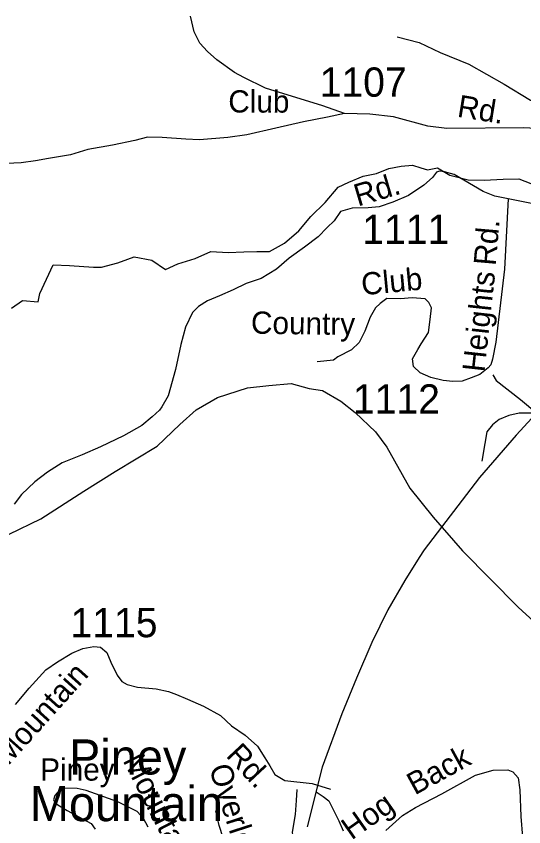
# Model space of a CAD drawing. Extents: x 990631 to 1056237, y 535999 to 585651.
# Drawn here: x 1027764 to 1029934, y 547537 to 550999 of the extents above; entities that cross this region are included whole.
import ezdxf

# ---------------------------------------------------------------- set-up
doc = ezdxf.new("R2010")
doc.units = 0
for name, color, linetype in [('Exist Boundary Political City Limit New', 7, 'Continuous'), ('Exist Geographical Mountain Summit Label', 7, 'Continuous'), ('Exist Hydrographic Creek Single Shore', 7, 'Continuous'), ('Exist Railroad Mainline', 7, 'Continuous'), ('Exist Road Non-System Type 51', 7, 'Continuous'), ('Exist Road Non-System Type 51 Label', 7, 'Continuous'), ('Exist Road Secondary Type 51 Attributed', 7, 'Continuous'), ('Exist Road Secondary Type 51 Label', 7, 'Continuous'), ('Exist Road Secondary Type 51 Number Label', 7, 'Continuous')]:
    doc.layers.add(name, color=color, linetype=linetype)

msp = doc.modelspace()

# ---------------------------------------------------------------- linework, layer by layer
at = {"layer": 'Exist Boundary Political City Limit New'}
msp.add_lwpolyline([(1030035.4, 549354.2), (1029900.6, 549210.2), (1029744.8, 549029.1), (1029507.9, 548720.2), (1029486.8, 548686.9), (1029425.4, 548588.9), (1029353.2, 548463.1), (1029284.4, 548323.4), (1029219.3, 548171.5), (1029156.2, 548019.5), (1029072.6, 547792.1), (1029008.1, 547536.1)], dxfattribs=at)
at = {"layer": 'Exist Hydrographic Creek Single Shore'}
for points in [[(1027743.5, 549751.9), (1027790.7, 549784.1), (1027857.7, 549778.7), (1027864.8, 549814.8), (1027922.2, 549937.5), (1027992.2, 549934.7), (1028094.7, 549927.7), (1028128.2, 549927.7), (1028199.2, 549945.5), (1028241, 549961.2), (1028268.6, 549970.7), (1028344.2, 549957.7), (1028402.4, 549917.6), (1028455.3, 549941.5), (1028529.5, 549964.8), (1028596.6, 549994.2), (1028670.5, 549989.4), (1028736.8, 549992.7), (1028792.8, 549994.5), (1028846.9, 549994.5), (1028910.3, 550030), (1028972.4, 550081.7), (1029022.8, 550143.9), (1029085, 550203.5), (1029139.7, 550269.5), (1029186.4, 550289.7), (1029247.6, 550315.4), (1029304, 550327.2), (1029356.9, 550349.2), (1029409.3, 550359.2), (1029457.5, 550363.3), (1029493.1, 550351.9), (1029522.8, 550342.7), (1029565.2, 550351)], [(1029565.2, 550351), (1029618.2, 550319.6), (1029696.3, 550300.2), (1029764.3, 550298.7), (1029846.2, 550303.4), (1029912.2, 550304), (1029964.4, 550284.3)]]:
    msp.add_lwpolyline(points, dxfattribs=at)
at = {"layer": 'Exist Railroad Mainline'}
msp.add_lwpolyline([(1027733.5, 548786.9), (1027868.8, 548852.7), (1028052.6, 548970.7), (1028186.7, 549053.7), (1028366.4, 549162.4), (1028463.2, 549254.9), (1028533.2, 549317.8), (1028625.1, 549371), (1028753.2, 549412.1), (1028844, 549421.9), (1028939.6, 549430.1), (1029016.8, 549409.6), (1029073.9, 549401), (1029151.9, 549354.1), (1029212.3, 549305.7), (1029299.3, 549223.5), (1029347.7, 549158.2), (1029447.1, 548983.5), (1029546.3, 548859.3), (1029671.7, 548715.2), (1029909.8, 548474.7), (1030127.3, 548276.1)], dxfattribs=at)
at = {"layer": 'Exist Road Non-System Type 51'}
for points in [[(1029167.7, 550582.9), (1029074.7, 550616), (1028829.2, 550692.2), (1028736.5, 550737.3), (1028697.3, 550758.7), (1028621, 550813.2), (1028582.3, 550848.6), (1028549.4, 550883.7), (1028524.9, 550932.4), (1028509.1, 550999.1)], [(1029392.8, 550911.5), (1029486.1, 550886.4), (1029576.9, 550844.5), (1029699.3, 550793.9), (1029850.3, 550708.5), (1029962.7, 550640.8), (1030104.1, 550567.1), (1030127, 550545.3), (1030135.5, 550510.3)], [(1029800.8, 549467.8), (1029816.1, 549443.3), (1029919.5, 549361.9), (1029989.8, 549303.5)], [(1029989.8, 549303.5), (1029913.7, 549304), (1029869.3, 549293.3), (1029828.8, 549276.7), (1029800.1, 549253.5), (1029775.1, 549224.4), (1029767.5, 549174.5), (1029755, 549099)], [(1029343.8, 547520.8), (1029415.9, 547584.5), (1029471, 547618.8), (1029583.3, 547677.5), (1029727.9, 547756.8), (1029802.8, 547778.5), (1029864.8, 547780.5), (1029886.5, 547771.8), (1029909.7, 547745.2), (1029916.1, 547694.8), (1029920.4, 547580.7), (1029927.6, 547492.3)], [(1028327.6, 547534.7), (1028308.8, 547571.5), (1028281.8, 547602.2), (1028199.2, 547643.1), (1028062.7, 547691.7), (1028024.9, 547701), (1027964.9, 547701.1), (1027948.7, 547693.6), (1027929.8, 547670.2), (1027923.3, 547652.3), (1027930.8, 547638.1), (1027981.8, 547606.3), (1028084.1, 547550.8), (1028101.2, 547526.2)], [(1029102.8, 546956.5), (1029064.4, 547007.8), (1029053.9, 547050.3), (1029049.2, 547086.4), (1029044.7, 547130.5), (1029047.9, 547170.4), (1029048.9, 547202.4), (1029032.8, 547255), (1028997.3, 547332.3), (1028965.4, 547397.4), (1028953, 547445.8), (1028945.4, 547514.2), (1028957.9, 547589.8), (1028961.7, 547649.7), (1028965.5, 547695.7)], [(1029045.9, 547686.3), (1029076.5, 547665.8), (1029099.9, 547647.1), (1029143, 547561.6), (1029161.5, 547518.9)], [(1028625.8, 546756.2), (1028634.8, 546782), (1028648.4, 546833.6), (1028650.3, 546889.6), (1028638.5, 546956), (1028622, 547000.6), (1028607.3, 547037.1), (1028596, 547061.5), (1028603, 547093.2), (1028624.1, 547126.6), (1028669.8, 547173.1), (1028690.5, 547196.5), (1028697.6, 547228.3), (1028692.5, 547312.4), (1028664.6, 547441.5), (1028632.1, 547542.5), (1028618.1, 547605)]]:
    msp.add_lwpolyline(points, dxfattribs=at)
at = {"layer": 'Exist Road Secondary Type 51 Attributed'}
for points in [[(1030135.5, 550510.3), (1029933.5, 550522.9), (1029604.1, 550519.8), (1029523.3, 550530), (1029376.8, 550569.4), (1029275.7, 550580.5), (1029167.7, 550582.9), (1029095.2, 550567.2), (1028992.5, 550548.6), (1028873.6, 550520.6), (1028750.4, 550492.7), (1028668.1, 550481.4), (1028547.7, 550471.4), (1028489.7, 550473.4), (1028387.5, 550481), (1028324.8, 550482.8), (1028271.3, 550468.1), (1028175.5, 550447.8), (1028070.4, 550429.3), (1027996.7, 550407.2), (1027902.5, 550390.8), (1027847.3, 550381.4), (1027784.7, 550372.2), (1027722, 550370.3)], [(1029866.7, 550218.6), (1029809.2, 550231), (1029759.7, 550250.4), (1029636.5, 550322.7), (1029595, 550334.8), (1029573.8, 550337.8), (1029560.7, 550332.8), (1029543.5, 550309.5), (1029507.1, 550277.2), (1029441.4, 550233.7), (1029373.7, 550204.4), (1029315.1, 550184.2), (1029268.7, 550180.1), (1029199.9, 550179.1), (1029150.4, 550165), (1029123.7, 550125.5), (1029093.2, 550096.3), (1029055.3, 550056.9), (1028997, 550013.2), (1028931.4, 549965.1), (1028876.1, 549918.4), (1028810.5, 549879.1), (1028746.4, 549857.2), (1028691, 549831), (1028632.8, 549804.7), (1028581.8, 549782.9), (1028543.9, 549759.5), (1028517.7, 549733.3), (1028487.1, 549670.6), (1028468.4, 549597.5), (1028444.9, 549490.1), (1028413, 549377.2), (1028386.5, 549330.9), (1028376.3, 549316.4), (1028345.7, 549287.2), (1028300.6, 549250.8), (1028223.4, 549207), (1028124.3, 549160.4), (1028045.6, 549125.4), (1027961.1, 549091.9), (1027898.5, 549051), (1027843.1, 549010.2), (1027786.3, 548956.3), (1027755.3, 548914.9)], [(1029866.7, 550218.6), (1029851.5, 549919.2), (1029814.3, 549606.5), (1029799.8, 549533.6), (1029792.5, 549510.3), (1029780.8, 549497.1), (1029746, 549468.8), (1029708.2, 549454.3), (1029670.9, 549440.2), (1029630.1, 549438.7), (1029589.3, 549443.6), (1029536.8, 549455.2), (1029491.4, 549475.5), (1029462.4, 549503.3), (1029457.6, 549536), (1029480.7, 549575.9), (1029495.3, 549599.2), (1029525.9, 549648.7), (1029533.2, 549704.1), (1029539, 549753.7), (1029527.3, 549775.6), (1029512.8, 549791.6), (1029455.9, 549796), (1029406.4, 549791.6), (1029349, 549793.4), (1029331.3, 549780.3), (1029320.2, 549771.3), (1029300.5, 549753.6), (1029277.6, 549713.7), (1029254.6, 549653.2), (1029230.5, 549604.9), (1029197.8, 549573.5), (1029138.3, 549543.8), (1029120.5, 549529.9), (1029050.4, 549522.7)], [(1030328.8, 550041.2), (1030272.2, 550034.1), (1030222.4, 550041), (1030156, 550061.8), (1030123.4, 550095.6), (1030035.2, 550175.4), (1029995.3, 550193.6), (1029866.7, 550218.6)], [(1027760.8, 548059), (1027819.8, 548128.8), (1027891.2, 548207), (1027940.4, 548241), (1028002.6, 548277.7), (1028049.3, 548298.1), (1028095.9, 548306.8), (1028125, 548303.9), (1028151.2, 548280.6), (1028168.7, 548239.7), (1028195.4, 548184), (1028215.8, 548157.8), (1028238.7, 548144.2), (1028282.4, 548132.5), (1028361.8, 548125.4), (1028414.5, 548115.2), (1028449.7, 548101.9), (1028496.3, 548081.5), (1028564, 548052.3), (1028637.1, 548011.5), (1028684.7, 547967.3), (1028742.8, 547927.8), (1028795.2, 547881.1), (1028827.3, 547831.6), (1028847.7, 547796.6), (1028869.9, 547759.9), (1028912.4, 547734.5), (1029029.8, 547722.2), (1029107, 547697.4)]]:
    msp.add_lwpolyline(points, dxfattribs=at)

# ---------------------------------------------------------------- texts
at = {"layer": 'Exist Geographical Mountain Summit Label'}
for s, p in [('   Piney', (1027822.7, 547760.1)), ('Mountain', (1027822.7, 547560.8))]:
    msp.add_text(s, height=150, dxfattribs=at).set_placement(p)
at = {"layer": 'Exist Road Non-System Type 51 Label'}
for s, rotation, p in [('Mountain', 297.1445, (1028218.2, 547820)), ('Back', 28.738, (1029467.9, 547670.3)), ('Piney', 359.989, (1027866.9, 547733.9)), ('Overlook', 287.8599, (1028587.4, 547788.2)), ('Hog ', 35.1676, (1029197.6, 547477.9))]:
    msp.add_text(s, height=95, rotation=rotation, dxfattribs=at).set_placement(p)
at = {"layer": 'Exist Road Secondary Type 51 Label'}
for s, rotation, p in [('Club', 359.8854, (1028670.6, 550587.8)), ('Rd.', 350.8651, (1029645.7, 550570.1)), ('Rd.', 16.5143, (1029224.3, 550185.8)), ('Rd.', 85.0677, (1029813.5, 549931.2)), ('Club', 5.468, (1029243.5, 549807)), ('Heights', 83.799, (1029765.3, 549476.5)), ('Country', 359.174, (1028767.2, 549643.3)), ('Mountain', 48.1286, (1027729.6, 547795)), ('Rd.', 313.1276, (1028657, 547838.4))]:
    msp.add_text(s, height=95, rotation=rotation, dxfattribs=at).set_placement(p)
at = {"layer": 'Exist Road Secondary Type 51 Number Label'}
for s, p in [('1107', (1029061.3, 550655.3)), ('1111', (1029243.5, 550026.7)), ('1112', (1029203.5, 549301.8)), ('1115', (1027996.3, 548346.5))]:
    msp.add_text(s, height=125, dxfattribs=at).set_placement(p)

doc.saveas('drawing.dxf')
